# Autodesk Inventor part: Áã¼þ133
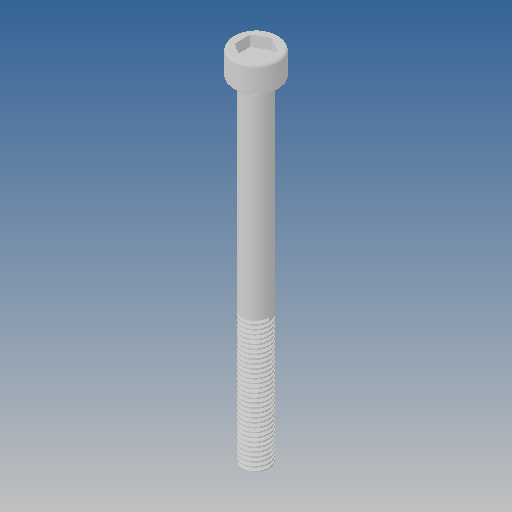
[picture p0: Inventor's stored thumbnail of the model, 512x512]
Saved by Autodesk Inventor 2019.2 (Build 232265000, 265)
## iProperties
Created: 2013-07
Part Number: Áã¼þ133
Material: Ogólny
Document SubType Name: Modeling
Designer: CADENGINEERING4
Density: 1 g/cm^3
Appearance: Domyślna
Author: CADENGINEERING4
Revision Number: ÈÎºÎ
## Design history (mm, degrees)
feature "ÇÐ³ý-É¨Ãè1"
node "Bryła1"
